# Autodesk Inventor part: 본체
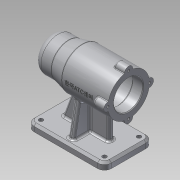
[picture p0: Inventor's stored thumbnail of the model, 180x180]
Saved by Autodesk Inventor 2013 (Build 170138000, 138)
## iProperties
Created: 2019-07
Part Number: 본체
Material: 알루미늄 6061
Document SubType Name: Modeling
Designer: Administrator
Density: 2.71 g/cm^3
Mass: 646.451 g
Surface Area: 654.972 cm^2
Volume: 238.543 cm^3
Author: Administrator
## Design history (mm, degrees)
sketch "스케치1"
  geometry: L1 (-56, 0)-(56, 0); L2 (-56, 0)-(-56, 25); L3 (-56, 25)-(-31, 25); L4 (-31, 25)-(-11, 30); L5 (-11, 30)-(56, 30); L6 (56, 30)-(56, 21); L7 (56, 21)-(41, 21); L8 (41, 21)-(41, 24); L9 (41, 24)-(-13, 24); L10 (-13, 24)-(-13, 21); L11 (-13, 21)-(-25, 21); L12 (-25, 21)-(-25, 17.5); L13 (-25, 17.5)-(-43, 17.5); L14 (-43, 17.5)-(-43, 16); L15 (-43, 16)-(-47, 16); L16 (-47, 16)-(-47, 10.5); L17 (-47, 10.5)-(-50, 10.5); L18 (-50, 10.5)-(-50, 0); 2 further points
  constraints: 36 end point, 9 horizontal, 8 vertical, 2 coincident, 1 collinear, 1 midpoint, 1 point on line, 1 vertical alignment
  dimensions: "d0" = 112 distance of L1.start L1.end; "d2" = 21 diameter of L17 L1; "d3" = 32 diameter of L15 L1; "d4" = 35 diameter of L13 L1; "d5" = 42 diameter of L11 L1; "d6" = 48 diameter of L9 L1; "d7" = 15 distance of L6.end L7.end; "d9" = 4 distance of L14.end L15.end; "d10" = 3 distance of L16.end L17.end; "d11" = 18 distance of L12.end L13.end; "d12" = 12 distance of L10.end L11.end; "d13" = 54 distance of L8.end L9.end; "d14" = 45 distance from line of L4.end L2; "d15" = 25 distance of L2.end L3.end; "d16" = 50 diameter of L3 L1; "d17" = 60 diameter of L5 L1
revolve "회전1" sketch "스케치1" stored, may be unused: angle "d18" = 90 deg
fillet "모깎기1" dims "d19" = 10
sketch "스케치2"
  geometry: C1 r 6 at (0, 30); 2 further points
  constraints: 1 centre point, 1 coincident, 1 vertical alignment, 1 other
  dimensions: "d20" = 12 diameter of C1
extrude "돌출1" join sketch "스케치2" distance "d22" = 16; taper "d23" = 0 deg
hole "구멍1" sketch "스케치2" diameter "d24" = 3.242; stored, may be unused: countersink angle "d28" = 90 deg, drill point angle "d30" = 118 deg; dims "d25" = 8, "d26" = 4, "d27" = 2, "d29" = 11
node "작업 평면1"
sketch "스케치3"
  geometry: L1 (-56, -35)-(56, -35); L2 (56, -35)-(56, 35); L3 (56, 35)-(-56, 35); L4 (-56, 35)-(-56, -35); L5 (-56, -35)-(56, 35); L6 (56, -35)-(-56, 35); 1 further point
  constraints: 12 end point, 2 midpoint, 2 parallel, 1 horizontal, 1 perpendicular
  dimensions: "d35" = 112 distance of L2.end L3.end; "d37" = 70 distance of L1.end L2.end
extrude "돌출2" join sketch "스케치3" distance "d38" = 10; taper "d39" = 0 deg
fillet "모깎기2" dims "d40" = 10
sketch "스케치4"
  geometry: L1 (-46, -25)-(46, -25); L2 (46, -25)-(46, 25); L3 (46, 25)-(-46, 25); L4 (-46, 25)-(-46, -25); L5 (-46, -25)-(46, 25); L6 (46, -25)-(-46, 25); 5 further points
  constraints: 12 end point, 4 coincident, 2 midpoint, 2 parallel, 1 horizontal, 1 perpendicular
  dimensions: "d41" = 92 distance of L2.end L3.end; "d43" = 50 distance of L3.end L1.start
hole "구멍2" sketch "스케치4" at (-46, 25), (-46, -25), (46, -25), (46, 25) diameter "d44" = 6; stored, may be unused: countersink angle "d48" = 90 deg, drill point angle "d50" = 118 deg; dims "d45" = 8, "d46" = 4, "d47" = 2, "d49" = 25
sketch "스케치5"
  geometry: L1 (-56, 25)-(-56, -25) reference; L2 (56, -25)-(56, 25) reference; L3 (46, 35)-(-46, 35) reference; L4 (-4, -28)-(4, -28); L5 (4, -28)-(4, 28); L6 (4, 28)-(-4, 28); L7 (-4, 28)-(-4, -28); L8 (-4, -28)-(4, 28); L9 (4, -28)-(-4, 28); L10 (-36, 4)-(31, 4); L11 (31, 4)-(31, -4); L12 (31, -4)-(-36, -4); L13 (-36, -4)-(-36, 4); 3 further points
  constraints: 20 end point, 4 midpoint, 4 parallel, 3 perpendicular, 2 horizontal, 1 horizontal alignment
  dimensions: "d51" = 20 distance between parallel lines of L13 L1; "d52" = 25 distance between parallel lines of L2 L11; "d53" = 8 distance of L5.end L6.end; "d54" = 7 distance between parallel lines of L6 L3
extrude "돌출3" join sketch "스케치5" stored distance "d55" = 10; taper "d56" = 0 deg
feature "면 기울기1" dims angle "d57" = 20 deg
fillet "모깎기5" dims "d60" = 0.3
chamfer "모따기1" distance "d61" = 3; stored, may be unused: second distance "d62" = 2, angle "d63" = 45 deg
feature "면 기울기2" dims angle "d64" = 10 deg
fillet "모깎기6" dims "d65" = 3
fillet "모깎기7" dims "d66" = 3
fillet "모깎기8" dims "d67" = 1
node "작업 평면3"
sketch "스케치7"
  geometry: L1 (33.5, 36)-(33.5, 30.171) reference; 2 further points
  constraints: 1 horizontal alignment, 1 other
  dimensions: "d68" = 42 distance from line of point (-8.5, 0) L1
feature "엠보싱1" sketch "스케치7" dims "d0" = 112, "d2" = 21, "d3" = 32, "d4" = 35, "d5" = 42, "d6" = 48, "d7" = 15, "d9" = 4, "d10" = 3, "d11" = 18, "d12" = 12, "d13" = 54, "d14" = 45, "d15" = 25, "d16" = 50, "d17" = 60, "d69" = 0.5, "d70" = 0
chamfer "모따기2" distance "d71" = 1; stored, may be unused: second distance "d72" = 2, angle "d73" = 45 deg
fillet "모깎기9" dims "d74" = 3
node "솔리드1"
pattern_circular "원형 패턴1" dims angle "d32" = 360 deg
